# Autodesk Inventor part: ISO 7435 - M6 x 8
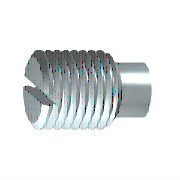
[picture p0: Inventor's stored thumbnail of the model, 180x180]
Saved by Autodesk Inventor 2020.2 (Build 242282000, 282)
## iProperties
Manager: www.cadconsulting.pl
Company: Fabian Stasiak CAD Consulting
Created: 2016-02
Part Number: ISO 7435 - M6 x 8
Material: Stal nierdzewna 440C
Description: Wkręty dociskowe z rowkiem z długim czopkiem
Document SubType Name: Modeling
Standard: ISO 7435
Designer: F.Stasiak
Standard Revision: First edition 1983-09-01
Standards Organization: ISO
Language: pl-PL
Size Designation: M6 x 8
Categories: <MemberInstance><Categories><Category DisplayName="Mocowania" InternalName="e4da775c-781d-43d5-af7c-5136215cf5a6" Mnemonic="FSTN"><Category DisplayName="Śruby"
Density: 7.75 g/cm^3
Appearance: Częściowo polerowana
IsCustomPart: 0
Author: F.Stasiak
Subject: Zbiór ćwiczeń. Autodesk Inventor 2020. Kurs podstawowy
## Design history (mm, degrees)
sketch "Szkic1"
  geometry: L1 (0, 0)-(8, 0); L2 (8, 0)-(8, 3); L3 (8, 3)-(3.25, 3); L4 (0, -0.6)-(0, 3.6) reference; L5 (0, 2)-(0, 0); L6 (0, 2)-(3.25, 2); L7 (3.25, 2)-(3.25, 3)
  constraints: 13 end point, 4 perpendicular, 2 parallel, 1 collinear, 1 point on line
  dimensions: "d1" = 8 distance from line of L2 L5.start (= NLG); "d2" = 4 diameter of L5.start L1 (= SPD); "d13" = 6 diameter of L3 L1 (= NND); "d14" = 3.25 distance of L5.start L6.end (= ZLG)
revolve "Bryła" sketch "Szkic1" stored, may be unused: angle "d6" = 90 deg
sketch "Szkic2"
  geometry: L1 (8, 2.387)-(8, -2.387) reference; L2 (6.08, 0)-(8.32, 0) reference; L3 (8, 0.5)-(6.4, 0.5); L4 (6.4, 0.5)-(6.4, 0); L5 (6.4, -0.5)-(6.4, 0); L6 (6.4, -0.5)-(8, -0.5)
  constraints: 8 end point, 3 point on line, 2 perpendicular, 1 parallel, 1 symmetric about line, 1 other
  dimensions: "d8" = 0.5 distance between parallel lines of L2 L3 (= 0.5 x SBR); "d9" = 1.6 distance between parallel lines of L1 L4 (= STI)
extrude "Szczelina" cut sketch "Szkic2" stored distance "d10" = 6 (= NND); taper "d11" = 0 deg
workaxis "Work Axis1"
workplane "Work Plane1"
body "Solid1"
chamfer "Faza1" distance "d3" = 0.61345 (= -0.5 x GD1 + 0.5 x NND); stored, may be unused: angle "d4" = 60 deg (= FAWI), second distance "d37" = 0.61345 (= -0.5 x GD1 + 0.5 x NND)
feature "Gwint" dims "d5" = 4.75 (= NLG - ZLG), "d7" = 0
chamfer "Faza2" distance "d15" = 1 (= -0.5 x SPD + 0.5 x NND); stored, may be unused: angle "d16" = 60 deg (= FAWI), second distance "d38" = 1 (= -0.5 x SPD + 0.5 x NND)
other parameters: "NND" = 6 [user parameter; used in 6 equation terms], "NLG" = 8 [user parameter; used in 2 equation terms], "FAWI" = 60 deg [user parameter; used in 2 equation terms], "GD1" = 4.7731 (= THREADDIA - 1.2269 x PTC) [user parameter; used in 2 equation terms], "d0" = 0, "FAWI1" = 45 deg [user parameter], "SPD" = 4 [user parameter; used in 3 equation terms], "SBR" = 1 [user parameter; used in 1 equation term], "STI" = 1.6 [user parameter; used in 1 equation term], "ZLG" = 3.25 [user parameter; used in 2 equation terms], "d17" = 0, "d39" = 90 deg, "d40" = 0, "GUL" = 0.61345 (= 0.61345 x PTC) [user parameter], "THREADDIA" = 6 [user parameter; used in 1 equation term], "TOA" = 30 deg [user parameter], "PTC" = 1 [user parameter; used in 4 equation terms], "GAL" = 0.61345 (= 0.61345 x PTC) [user parameter]
